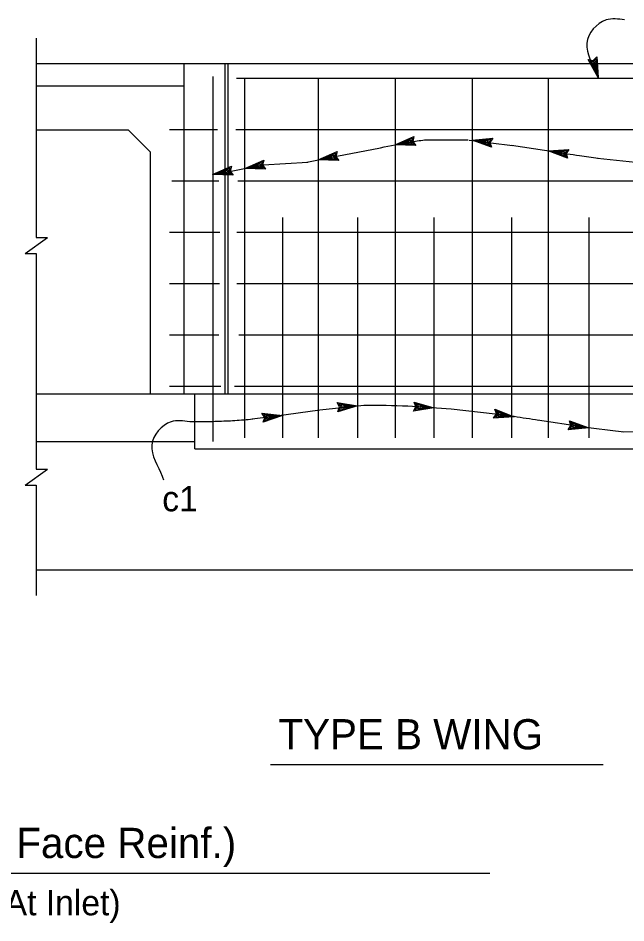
# Model space of a CAD drawing. Extents: x -0.08 to 2.83, y -0.03 to 1.92.
# Drawn here: x 0.6463 to 0.9609, y 0.5912 to 1.0591 of the extents above; entities that cross this region are included whole.
import ezdxf

# ---------------------------------------------------------------- set-up
doc = ezdxf.new("R2010")
doc.units = 0
for name, color, linetype in [('50', 7, 'Continuous'), ('51', 7, 'Continuous'), ('55', 7, 'Continuous'), ('57', 7, 'Continuous')]:
    doc.layers.add(name, color=color, linetype=linetype)

msp = doc.modelspace()

# ---------------------------------------------------------------- linework, layer by layer
at = {"layer": '50'}
for p, q in [((0.65571, 1.03566), (1.05185, 1.03566)), ((0.73211, 1.03566), (0.73211, 0.86474)), ((0.75328, 1.03566), (0.75328, 0.86474)), ((0.75494, 1.03566), (0.75494, 0.86474)), ((0.65571, 1.024), (0.73211, 1.024)), ((0.65571, 1.00125), (0.70332, 1.00125)), ((0.70332, 1.00125), (0.7147, 0.98987)), ((0.7147, 0.98987), (0.7147, 0.86474)), ((0.6557, 0.86474), (1.05185, 0.86474)), ((0.73779, 0.8363), (0.73779, 0.86474)), ((0.6557, 0.84009), (0.73779, 0.84009)), ((0.73779, 0.8363), (1.05185, 0.8363)), ((0.65571, 0.77373), (1.05185, 0.77373))]:
    msp.add_line(p, q, dxfattribs=at)
at = {"layer": '51'}
for p, q in [((0.74718, 1.02884), (0.74718, 0.84009)), ((0.75938, 1.02808), (1.0471, 1.02808)), ((0.76345, 1.02808), (0.76345, 0.84199)), ((0.80165, 1.02808), (0.80165, 0.84199)), ((0.84138, 1.02808), (0.84138, 0.84199)), ((0.88126, 1.02808), (0.88126, 0.84199)), ((0.92071, 1.02808), (0.92071, 0.84199)), ((0.72475, 1.00153), (0.74944, 1.00153)), ((0.75892, 1.00153), (1.0471, 1.00153)), ((0.72592, 0.97499), (0.75015, 0.97499)), ((0.75997, 0.97499), (1.0471, 0.97499)), ((0.78322, 0.956), (0.78322, 0.84199)), ((0.82204, 0.956), (0.82204, 0.84199)), ((0.86153, 0.956), (0.86153, 0.84199)), ((0.90174, 0.956), (0.90174, 0.84199)), ((0.9417, 0.956), (0.9417, 0.84199)), ((0.72475, 0.94845), (0.75065, 0.94845)), ((0.75944, 0.94845), (1.0471, 0.94845)), ((0.72475, 0.92191), (0.75059, 0.92191)), ((0.75944, 0.92191), (1.0471, 0.92191)), ((0.72475, 0.89537), (0.75017, 0.89537)), ((0.76049, 0.89537), (1.0471, 0.89537)), ((0.72475, 0.86882), (0.75125, 0.86882)), ((0.75839, 0.86882), (1.0471, 0.86882))]:
    msp.add_line(p, q, dxfattribs=at)
at = {"layer": '55'}
for p, q in [((0.65571, 1.04865), (0.6557, 0.94564)), ((0.9439, 1.03725), (0.94584, 1.03901)), ((0.94584, 1.03901), (0.94657, 1.02831)), ((0.94657, 1.02831), (0.94133, 1.03767)), ((0.94133, 1.03767), (0.9439, 1.03725)), ((0.94657, 1.02831), (0.94214, 1.03705)), ((0.94214, 1.03705), (0.9441, 1.03659)), ((0.94617, 1.02962), (0.94331, 1.03605)), ((0.94331, 1.03605), (0.94429, 1.03594)), ((0.9441, 1.03659), (0.94551, 1.03797)), ((0.94576, 1.03155), (0.94419, 1.0352)), ((0.94419, 1.0352), (0.94477, 1.03459)), ((0.94429, 1.03594), (0.9453, 1.0368)), ((0.94477, 1.03459), (0.94507, 1.03546)), ((0.94521, 1.03337), (0.94494, 1.03432)), ((0.94507, 1.03546), (0.94521, 1.03337)), ((0.9453, 1.0368), (0.94576, 1.03155)), ((0.94551, 1.03797), (0.94617, 1.02962)), ((0.84138, 0.99352), (0.8512, 0.99783)), ((0.84138, 0.99352), (0.8505, 0.99709)), ((0.8505, 0.99709), (0.84987, 0.99518)), ((0.8512, 0.99783), (0.85053, 0.99531)), ((0.88126, 0.99592), (0.89195, 0.99697)), ((0.89195, 0.99697), (0.89053, 0.99477)), ((0.81126, 0.98765), (0.83385, 0.99206)), ((0.8521, 0.99321), (0.84138, 0.99352)), ((0.84272, 0.99379), (0.84939, 0.99601)), ((0.85109, 0.99364), (0.84272, 0.99379)), ((0.84468, 0.99401), (0.84847, 0.99522)), ((0.84995, 0.99396), (0.84468, 0.99401)), ((0.84654, 0.99438), (0.84751, 0.99456)), ((0.84864, 0.99432), (0.84654, 0.99438)), ((0.84847, 0.99522), (0.84779, 0.9947)), ((0.84779, 0.9947), (0.84864, 0.99432)), ((0.84939, 0.99601), (0.8492, 0.99505)), ((0.8492, 0.99505), (0.84995, 0.99396)), ((0.84987, 0.99518), (0.85109, 0.99364)), ((0.85053, 0.99531), (0.8521, 0.99321)), ((0.85684, 0.99616), (0.87932, 0.9961)), ((0.87967, 0.99607), (0.90213, 0.99329)), ((0.88126, 0.99592), (0.89104, 0.99647)), ((0.89136, 0.9923), (0.88126, 0.99592)), ((0.88263, 0.99576), (0.88966, 0.9958)), ((0.89054, 0.99302), (0.88263, 0.99576)), ((0.88955, 0.99368), (0.88456, 0.99537)), ((0.88456, 0.99537), (0.88853, 0.99533)), ((0.88842, 0.99443), (0.88644, 0.99514)), ((0.88644, 0.99514), (0.88742, 0.99501)), ((0.88853, 0.99533), (0.88773, 0.99505)), ((0.88773, 0.99505), (0.88842, 0.99443)), ((0.88966, 0.9958), (0.88917, 0.99495)), ((0.88917, 0.99495), (0.88955, 0.99368)), ((0.89104, 0.99647), (0.88985, 0.99486)), ((0.88985, 0.99486), (0.89054, 0.99302)), ((0.89053, 0.99477), (0.89136, 0.9923)), ((0.90162, 0.99337), (0.92443, 0.98992)), ((0.79577, 0.98463), (0.81118, 0.98764)), ((0.80165, 0.98578), (0.81147, 0.99009)), ((0.80165, 0.98578), (0.81077, 0.98934)), ((0.80299, 0.98604), (0.80966, 0.98827)), ((0.80495, 0.98627), (0.80874, 0.98747)), ((0.80874, 0.98747), (0.80806, 0.98696)), ((0.80966, 0.98827), (0.80947, 0.98731)), ((0.80947, 0.98731), (0.81022, 0.98622)), ((0.81077, 0.98934), (0.81014, 0.98744)), ((0.81014, 0.98744), (0.81136, 0.9859)), ((0.81147, 0.99009), (0.8108, 0.98757)), ((0.8108, 0.98757), (0.81237, 0.98547)), ((0.92071, 0.99049), (0.93141, 0.99124)), ((0.92071, 0.99049), (0.93049, 0.99078)), ((0.93071, 0.9866), (0.92071, 0.99049)), ((0.9299, 0.98733), (0.92205, 0.99028)), ((0.92205, 0.99028), (0.92909, 0.99014)), ((0.92892, 0.98802), (0.92399, 0.98984)), ((0.92399, 0.98984), (0.92795, 0.9897)), ((0.92782, 0.9888), (0.92586, 0.98955)), ((0.92586, 0.98955), (0.92683, 0.98941)), ((0.92795, 0.9897), (0.92714, 0.98944)), ((0.92714, 0.98944), (0.92782, 0.9888)), ((0.92909, 0.99014), (0.92858, 0.9893)), ((0.92858, 0.9893), (0.92892, 0.98802)), ((0.93049, 0.99078), (0.92926, 0.9892)), ((0.92926, 0.9892), (0.9299, 0.98733)), ((0.93141, 0.99124), (0.92993, 0.98909)), ((0.92993, 0.98909), (0.93071, 0.9866)), ((0.75042, 0.97876), (0.77317, 0.9832)), ((0.7636, 0.98137), (0.77341, 0.98568)), ((0.7636, 0.98137), (0.77272, 0.98492)), ((0.76494, 0.98162), (0.77161, 0.98385)), ((0.7669, 0.98186), (0.77069, 0.98306)), ((0.77069, 0.98306), (0.77001, 0.98254)), ((0.77161, 0.98385), (0.77142, 0.98289)), ((0.77142, 0.98289), (0.77217, 0.9818)), ((0.77272, 0.98492), (0.77208, 0.98302)), ((0.77208, 0.98302), (0.77331, 0.98148)), ((0.77341, 0.98568), (0.77275, 0.98315)), ((0.77275, 0.98315), (0.77432, 0.98107)), ((0.77316, 0.98324), (0.7963, 0.98465)), ((0.81237, 0.98547), (0.80165, 0.98578)), ((0.81136, 0.9859), (0.80299, 0.98604)), ((0.81022, 0.98622), (0.80495, 0.98627)), ((0.80681, 0.98664), (0.80779, 0.98682)), ((0.80891, 0.98658), (0.80681, 0.98664)), ((0.80806, 0.98696), (0.80891, 0.98658)), ((0.94623, 0.98673), (0.96903, 0.98423)), ((0.74689, 0.97815), (0.75671, 0.98246)), ((0.74689, 0.97815), (0.75602, 0.9817)), ((0.75762, 0.97785), (0.74689, 0.97815)), ((0.74823, 0.9784), (0.75491, 0.98063)), ((0.75661, 0.97826), (0.74823, 0.9784)), ((0.7502, 0.97864), (0.75399, 0.97984)), ((0.75546, 0.97858), (0.7502, 0.97864)), ((0.75206, 0.97899), (0.75303, 0.97919)), ((0.75416, 0.97894), (0.75206, 0.97899)), ((0.75399, 0.97984), (0.75331, 0.97932)), ((0.75331, 0.97932), (0.75416, 0.97894)), ((0.75491, 0.98063), (0.75471, 0.97967)), ((0.75471, 0.97967), (0.75546, 0.97858)), ((0.75602, 0.9817), (0.75538, 0.9798)), ((0.75538, 0.9798), (0.75661, 0.97826)), ((0.75671, 0.98246), (0.75605, 0.97993)), ((0.75605, 0.97993), (0.75762, 0.97785)), ((0.77432, 0.98107), (0.7636, 0.98137)), ((0.77331, 0.98148), (0.76494, 0.98162)), ((0.77217, 0.9818), (0.7669, 0.98186)), ((0.76876, 0.98221), (0.76973, 0.98241)), ((0.77086, 0.98216), (0.76876, 0.98221)), ((0.77001, 0.98254), (0.77086, 0.98216)), ((0.64992, 0.93733), (0.6615, 0.94564)), ((0.6557, 0.94564), (0.6615, 0.94564)), ((0.64992, 0.93733), (0.65571, 0.93733)), ((0.65571, 0.93733), (0.6557, 0.82594)), ((0.80255, 0.85645), (0.78001, 0.85323)), ((0.8253, 0.85886), (0.80255, 0.85645)), ((0.81273, 0.85802), (0.81144, 0.86029)), ((0.81144, 0.86029), (0.82204, 0.85867)), ((0.82204, 0.85867), (0.81176, 0.85559)), ((0.81176, 0.85559), (0.81273, 0.85802)), ((0.81341, 0.85806), (0.81238, 0.85974)), ((0.81238, 0.85974), (0.82067, 0.85858)), ((0.82204, 0.85867), (0.81255, 0.85626)), ((0.81255, 0.85626), (0.81341, 0.85806)), ((0.8141, 0.85811), (0.81348, 0.85928)), ((0.81348, 0.85928), (0.8187, 0.85859)), ((0.82067, 0.85858), (0.81378, 0.85717)), ((0.81378, 0.85717), (0.8141, 0.85811)), ((0.81552, 0.85829), (0.81474, 0.85877)), ((0.81474, 0.85877), (0.81681, 0.85846)), ((0.8187, 0.85859), (0.8148, 0.85786)), ((0.8148, 0.85786), (0.81552, 0.85829)), ((0.81681, 0.85846), (0.81583, 0.85839)), ((0.87047, 0.85687), (0.84784, 0.85838)), ((0.85093, 0.85585), (0.85223, 0.85812)), ((0.86153, 0.8575), (0.85093, 0.85585)), ((0.85223, 0.85812), (0.85125, 0.86054)), ((0.85125, 0.86054), (0.86153, 0.8575)), ((0.8518, 0.8564), (0.85291, 0.85808)), ((0.86153, 0.8575), (0.8518, 0.8564)), ((0.85291, 0.85808), (0.85212, 0.85987)), ((0.85212, 0.85987), (0.86017, 0.85759)), ((0.85359, 0.85803), (0.85314, 0.85928)), ((0.85314, 0.85928), (0.85822, 0.85788)), ((0.85315, 0.85714), (0.85359, 0.85803)), ((0.86017, 0.85759), (0.85315, 0.85714)), ((0.85425, 0.85768), (0.85504, 0.85801)), ((0.85822, 0.85788), (0.85425, 0.85768)), ((0.85504, 0.85801), (0.85431, 0.85859)), ((0.85431, 0.85859), (0.85632, 0.858)), ((0.85632, 0.858), (0.85534, 0.85806)), ((0.89327, 0.85438), (0.87047, 0.85687)), ((0.89387, 0.85439), (0.89309, 0.85688)), ((0.89309, 0.85688), (0.90309, 0.85299)), ((0.78001, 0.85323), (0.76746, 0.85163)), ((0.77395, 0.85255), (0.77254, 0.85474)), ((0.77254, 0.85474), (0.78322, 0.85369)), ((0.78322, 0.85369), (0.77312, 0.85008)), ((0.77312, 0.85008), (0.77395, 0.85255)), ((0.77463, 0.85264), (0.77352, 0.85425)), ((0.77352, 0.85425), (0.78185, 0.85353)), ((0.78322, 0.85369), (0.77386, 0.85078)), ((0.77386, 0.85078), (0.77463, 0.85264)), ((0.77531, 0.85272), (0.77464, 0.85385)), ((0.77464, 0.85385), (0.77989, 0.85343)), ((0.78185, 0.85353), (0.77504, 0.85177)), ((0.77504, 0.85177), (0.77531, 0.85272)), ((0.77673, 0.85297), (0.77592, 0.8534)), ((0.77592, 0.8534), (0.778, 0.8532)), ((0.77989, 0.85343), (0.77603, 0.8525)), ((0.77603, 0.8525), (0.77673, 0.85297)), ((0.778, 0.8532), (0.77703, 0.85309)), ((0.89239, 0.85224), (0.89387, 0.85439)), ((0.90309, 0.85299), (0.89239, 0.85224)), ((0.8933, 0.8527), (0.89454, 0.85428)), ((0.90309, 0.85299), (0.8933, 0.8527)), ((0.89454, 0.85428), (0.8939, 0.85615)), ((0.8939, 0.85615), (0.90174, 0.8532)), ((0.89471, 0.85334), (0.89521, 0.85418)), ((0.90174, 0.8532), (0.89471, 0.85334)), ((0.89521, 0.85418), (0.89488, 0.85546)), ((0.89488, 0.85546), (0.89981, 0.85364)), ((0.89584, 0.85378), (0.89666, 0.85404)), ((0.89981, 0.85364), (0.89584, 0.85378)), ((0.89666, 0.85404), (0.89598, 0.85468)), ((0.89598, 0.85468), (0.89793, 0.85393)), ((0.89793, 0.85393), (0.89697, 0.85407)), ((0.938, 0.84772), (0.91519, 0.85117)), ((0.93101, 0.84621), (0.93243, 0.8484)), ((0.9417, 0.84726), (0.93101, 0.84621)), ((0.93243, 0.8484), (0.9316, 0.85087)), ((0.9316, 0.85087), (0.9417, 0.84726)), ((0.93192, 0.8467), (0.93311, 0.84832)), ((0.9417, 0.84726), (0.93192, 0.8467)), ((0.93311, 0.84832), (0.93242, 0.85016)), ((0.93242, 0.85016), (0.94033, 0.84742)), ((0.9333, 0.84738), (0.93379, 0.84823)), ((0.94033, 0.84742), (0.9333, 0.84738)), ((0.93379, 0.84823), (0.93341, 0.8495)), ((0.93341, 0.8495), (0.9384, 0.84781)), ((0.93443, 0.84785), (0.93523, 0.84813)), ((0.9384, 0.84781), (0.93443, 0.84785)), ((0.93523, 0.84813), (0.93454, 0.84875)), ((0.93454, 0.84875), (0.93652, 0.84804)), ((0.93652, 0.84804), (0.93554, 0.84816)), ((0.95974, 0.84505), (0.93728, 0.84783)), ((0.98176, 0.84503), (0.95928, 0.84509)), ((0.64992, 0.81763), (0.6615, 0.82594)), ((0.6557, 0.82594), (0.6615, 0.82594)), ((0.64992, 0.81763), (0.65571, 0.81763)), ((0.65571, 0.81763), (0.65571, 0.76055))]:
    msp.add_line(p, q, dxfattribs=at)
for points in [[(0.9602, 1.05814), (0.95057, 1.05814), (0.94063, 1.04616), (0.94589, 1.03009), (0.94658, 1.02807)], [(0.83388, 0.99206), (0.84907, 0.99502), (0.85668, 0.99615)], [(0.92419, 0.98996), (0.93679, 0.98805), (0.94655, 0.98668)], [(0.84797, 0.85837), (0.82566, 0.85886), (0.8253, 0.85886)], [(0.7678, 0.85167), (0.75848, 0.85089), (0.75392, 0.85066)], [(0.91563, 0.8511), (0.90303, 0.85301), (0.89327, 0.85438)], [(0.73512, 0.85034), (0.72549, 0.85034), (0.71555, 0.83836), (0.72081, 0.82229), (0.72149, 0.82027)], [(0.75392, 0.85066), (0.74457, 0.85034), (0.73512, 0.85034)]]:
    msp.add_spline(points, degree=3, dxfattribs=at)
at = {"layer": '57'}
for p, q in [((0.77696, 0.67316), (0.94905, 0.67316)), ((0.45655, 0.61696), (0.89051, 0.61696))]:
    msp.add_line(p, q, dxfattribs=at)

# ---------------------------------------------------------------- texts
for s, height, p in [('c1', 0.013021, (0.72093, 0.80406)), ('TYPE B WING', 0.015625, (0.78105, 0.68097)), ('ELEVATION (Back Face Reinf.)', 0.015625, (0.46312, 0.62477)), ('(Shown At Inlet)', 0.0130208, (0.5755, 0.59515))]:
    msp.add_text(s, height=height, dxfattribs=at).set_placement(p)

doc.saveas('drawing.dxf')
